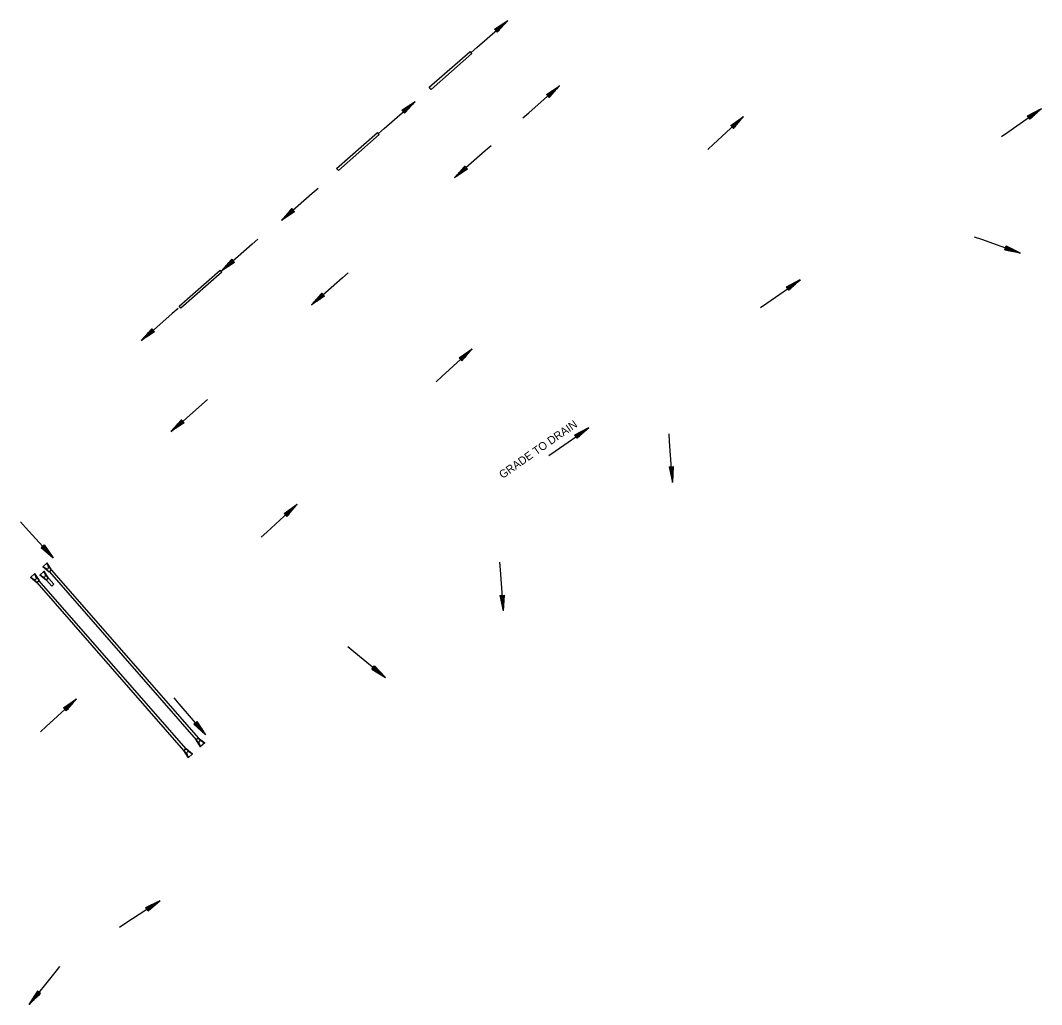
# Model space of a CAD drawing. Extents: x 1308292 to 1312792, y 238563 to 242743.
# Drawn here: x 1309034 to 1309800, y 239274 to 240011 of the extents above; entities that cross this region are included whole.
import ezdxf

# ---------------------------------------------------------------- set-up
doc = ezdxf.new("R2010")
doc.units = 0
for name, color, linetype in [('R_FES', 7, 'Continuous'), ('R_Flow Arrows', 7, 'Continuous'), ('R_Pipe Culvert', 7, 'Continuous')]:
    doc.layers.add(name, color=color, linetype=linetype)

msp = doc.modelspace()

# ---------------------------------------------------------------- linework, layer by layer
at = {"layer": 'R_FES'}
for p, q in [((1309051.19, 239601.87), (1309054.59, 239604.82)), ((1309055.54, 239601.86), (1309054.4, 239604.65)), ((1309057.54, 239599.55), (1309054.4, 239604.65)), ((1309057.85, 239599.54), (1309054.59, 239604.82)), ((1309054.59, 239604.82), (1309055.54, 239601.86)), ((1309042.01, 239593.8), (1309045.36, 239596.81)), ((1309046.36, 239593.87), (1309045.17, 239596.64)), ((1309048.41, 239591.6), (1309045.17, 239596.64)), ((1309048.71, 239591.59), (1309045.36, 239596.81)), ((1309045.36, 239596.81), (1309046.36, 239593.87)), ((1309048.89, 239595.75), (1309052.27, 239598.72)), ((1309049.08, 239595.91), (1309051.72, 239594.25)), ((1309053.71, 239592.11), (1309049.08, 239595.91)), ((1309055.96, 239597.9), (1309051.19, 239601.87)), ((1309054, 239600.36), (1309051.19, 239601.87)), ((1309051.38, 239602.04), (1309054, 239600.36)), ((1309055.98, 239598.2), (1309051.38, 239602.04)), ((1309053.24, 239595.76), (1309052.08, 239598.55)), ((1309055.26, 239593.47), (1309052.08, 239598.55)), ((1309055.56, 239593.46), (1309052.27, 239598.72)), ((1309052.27, 239598.72), (1309053.24, 239595.76)), ((1309057.85, 239599.54), (1309055.96, 239597.9)), ((1309055.98, 239598.2), (1309055.96, 239597.9)), ((1309055.98, 239598.2), (1309057.54, 239599.55)), ((1309057.54, 239599.55), (1309057.85, 239599.54)), ((1309046.85, 239589.92), (1309042.01, 239593.8)), ((1309044.85, 239592.34), (1309042.01, 239593.8)), ((1309042.2, 239593.97), (1309044.85, 239592.34)), ((1309046.87, 239590.22), (1309042.2, 239593.97)), ((1309048.71, 239591.59), (1309046.85, 239589.92)), ((1309046.87, 239590.22), (1309046.85, 239589.92)), ((1309046.87, 239590.22), (1309048.41, 239591.6)), ((1309048.41, 239591.6), (1309048.71, 239591.59)), ((1309053.69, 239591.81), (1309048.89, 239595.75)), ((1309051.72, 239594.25), (1309048.89, 239595.75)), ((1309055.56, 239593.46), (1309053.69, 239591.81)), ((1309053.71, 239592.11), (1309053.69, 239591.81)), ((1309053.71, 239592.11), (1309055.26, 239593.47)), ((1309055.26, 239593.47), (1309055.56, 239593.46)), ((1309165.89, 239472.22), (1309167.76, 239473.88)), ((1309167.74, 239473.57), (1309166.19, 239472.21)), ((1309167.74, 239473.57), (1309167.76, 239473.88)), ((1309167.74, 239473.57), (1309172.37, 239469.77)), ((1309167.76, 239473.88), (1309172.56, 239469.94)), ((1309156.74, 239464.17), (1309158.62, 239465.82)), ((1309158.59, 239465.52), (1309158.62, 239465.82)), ((1309158.62, 239465.82), (1309163.41, 239461.88)), ((1309165.89, 239472.22), (1309169.18, 239466.96)), ((1309166.19, 239472.21), (1309165.89, 239472.22)), ((1309166.19, 239472.21), (1309169.37, 239467.13)), ((1309168.21, 239469.92), (1309169.37, 239467.13)), ((1309169.18, 239466.96), (1309168.21, 239469.92)), ((1309172.56, 239469.94), (1309169.18, 239466.96)), ((1309169.73, 239471.43), (1309172.56, 239469.94)), ((1309172.37, 239469.77), (1309169.73, 239471.43)), ((1309156.74, 239464.17), (1309160.03, 239458.91)), ((1309157.04, 239464.16), (1309156.74, 239464.17)), ((1309158.59, 239465.52), (1309157.04, 239464.16)), ((1309157.04, 239464.16), (1309160.22, 239459.08)), ((1309158.59, 239465.52), (1309163.22, 239461.71)), ((1309159.07, 239461.86), (1309160.22, 239459.08)), ((1309160.03, 239458.91), (1309159.07, 239461.86)), ((1309163.41, 239461.88), (1309160.03, 239458.91)), ((1309160.59, 239463.37), (1309163.41, 239461.88)), ((1309163.22, 239461.71), (1309160.59, 239463.37))]:
    msp.add_line(p, q, dxfattribs=at)
for centre, major_axis in [((1309054.45, 239601.44), (-0.787, 0.862)), ((1309045.28, 239593.43), (-0.803, 0.846)), ((1309052.15, 239595.34), (-0.793, 0.856)), ((1309169.3, 239470.34), (0.793, -0.856)), ((1309160.15, 239462.29), (0.793, -0.856))]:
    msp.add_ellipse(centre, major_axis=major_axis, ratio=0.999949, start_param=2.010439, end_param=4.34099, dxfattribs=at)
at = {"layer": 'R_Flow Arrows'}
for p, q in [((1309389.78, 240004.61), (1309399.62, 240011.2)), ((1309391.78, 240002.32), (1309399.62, 240011.2)), ((1309389.78, 240004.61), (1309391.78, 240002.32)), ((1309428.61, 239955.75), (1309438.51, 239962.26)), ((1309428.61, 239955.75), (1309430.59, 239953.45)), ((1309430.59, 239953.45), (1309438.51, 239962.26)), ((1309320.34, 239943.9), (1309330.18, 239950.49)), ((1309322.34, 239941.61), (1309330.18, 239950.49)), ((1309320.34, 239943.9), (1309322.34, 239941.61)), ((1309789.1, 239939.65), (1309799.55, 239945.23)), ((1309790.86, 239937.17), (1309799.55, 239945.23)), ((1309566.69, 239932.4), (1309576.37, 239939.23)), ((1309568.74, 239930.16), (1309576.37, 239939.23)), ((1309790.86, 239937.17), (1309789.1, 239939.65)), ((1309566.69, 239932.4), (1309568.74, 239930.16)), ((1309367.56, 239902.12), (1309359.64, 239893.31)), ((1309369.54, 239899.82), (1309367.56, 239902.12)), ((1309369.54, 239899.82), (1309359.64, 239893.31)), ((1309237.92, 239870.22), (1309230, 239861.4)), ((1309239.9, 239867.91), (1309230, 239861.4)), ((1309239.9, 239867.91), (1309237.92, 239870.22)), ((1309772.02, 239839.47), (1309773.01, 239842.35)), ((1309773.01, 239842.35), (1309783.63, 239837.09)), ((1309772.02, 239839.47), (1309783.63, 239837.09)), ((1309192.87, 239832.29), (1309184.95, 239823.47)), ((1309194.85, 239829.98), (1309184.95, 239823.47)), ((1309194.85, 239829.98), (1309192.87, 239832.29)), ((1309608.4, 239811.51), (1309618.85, 239817.09)), ((1309610.16, 239809.04), (1309608.4, 239811.51)), ((1309610.16, 239809.04), (1309618.85, 239817.09)), ((1309260.41, 239806.9), (1309252.5, 239798.08)), ((1309262.39, 239804.59), (1309252.5, 239798.08)), ((1309262.39, 239804.59), (1309260.41, 239806.9)), ((1309132.96, 239780.2), (1309125.04, 239771.38)), ((1309134.94, 239777.89), (1309132.96, 239780.2)), ((1309134.94, 239777.89), (1309125.04, 239771.38)), ((1309363.25, 239758.42), (1309372.93, 239765.24)), ((1309365.3, 239756.18), (1309372.93, 239765.24)), ((1309363.25, 239758.42), (1309365.3, 239756.18)), ((1309155.14, 239712.05), (1309147.22, 239703.23)), ((1309157.12, 239709.74), (1309155.14, 239712.05)), ((1309157.12, 239709.74), (1309147.22, 239703.23)), ((1309449.89, 239700.65), (1309460.34, 239706.23)), ((1309451.66, 239698.17), (1309460.34, 239706.23)), ((1309451.66, 239698.17), (1309449.89, 239700.65)), ((1309520.58, 239676.66), (1309523.61, 239676.92)), ((1309520.58, 239676.66), (1309523.07, 239665.08)), ((1309523.61, 239676.92), (1309523.07, 239665.08)), ((1309232.14, 239641.88), (1309241.83, 239648.7)), ((1309232.14, 239641.88), (1309234.2, 239639.64)), ((1309234.2, 239639.64), (1309241.83, 239648.7)), ((1309052.23, 239618.35), (1309049.98, 239616.3)), ((1309049.98, 239616.3), (1309059.01, 239608.63)), ((1309052.23, 239618.35), (1309059.01, 239608.63)), ((1309393.79, 239580.47), (1309396.82, 239580.72)), ((1309396.82, 239580.72), (1309396.29, 239568.89)), ((1309393.79, 239580.47), (1309396.29, 239568.89)), ((1309297.89, 239525.23), (1309299.8, 239527.59)), ((1309299.8, 239527.59), (1309307.99, 239519.04)), ((1309297.89, 239525.23), (1309307.99, 239519.04)), ((1309066.77, 239496.16), (1309076.45, 239502.99)), ((1309068.82, 239493.92), (1309076.45, 239502.99)), ((1309066.77, 239496.16), (1309068.82, 239493.92)), ((1309166.69, 239485.99), (1309164.39, 239484.01)), ((1309164.39, 239484.01), (1309173.22, 239476.11)), ((1309166.69, 239485.99), (1309173.22, 239476.11)), ((1309128.53, 239346.79), (1309139.16, 239352.02)), ((1309130.21, 239344.26), (1309139.16, 239352.02)), ((1309130.21, 239344.26), (1309128.53, 239346.79)), ((1309047.12, 239284.1), (1309040.86, 239274.04)), ((1309049.48, 239282.17), (1309040.86, 239274.04)), ((1309049.48, 239282.17), (1309047.12, 239284.1))]:
    msp.add_line(p, q, dxfattribs=at)
for points in [[(1309372.16, 239987.17), (1309376.49, 239990.98), (1309399.62, 240011.2)], [(1309390.58, 240003.7), (1309395.26, 240007.79), (1309397.66, 240009.88)], [(1309390.98, 240003.24), (1309395.66, 240007.33), (1309398.06, 240009.42)], [(1309389.98, 240004.38), (1309391.75, 240005.93)], [(1309390.18, 240004.15), (1309393.71, 240007.25)], [(1309390.38, 240003.93), (1309395.06, 240008.02), (1309395.69, 240008.57)], [(1309391.18, 240003.01), (1309395.86, 240007.1), (1309396.48, 240007.65)], [(1309391.38, 240002.78), (1309394.92, 240005.88)], [(1309391.58, 240002.55), (1309393.35, 240004.1)], [(1309411.01, 239938.28), (1309415.32, 239942.1), (1309438.41, 239962.38)], [(1309428.81, 239955.52), (1309430.59, 239957.06)], [(1309429.01, 239955.29), (1309432.57, 239958.36)], [(1309429.2, 239955.06), (1309433.92, 239959.12), (1309434.55, 239959.66)], [(1309429.4, 239954.83), (1309434.12, 239958.89), (1309436.53, 239960.96)], [(1309429.8, 239954.37), (1309434.51, 239958.43), (1309436.93, 239960.49)], [(1309430, 239954.14), (1309434.71, 239958.2), (1309435.34, 239958.74)], [(1309430.2, 239953.91), (1309433.76, 239956.98)], [(1309302.73, 239926.46), (1309307.05, 239930.27), (1309330.18, 239950.49)], [(1309320.94, 239943.21), (1309325.62, 239947.31), (1309326.25, 239947.85)], [(1309321.14, 239942.99), (1309325.82, 239947.08), (1309328.22, 239949.17)], [(1309321.54, 239942.53), (1309326.22, 239946.62), (1309328.62, 239948.71)], [(1309430.39, 239953.68), (1309432.18, 239955.21)], [(1309320.54, 239943.67), (1309322.31, 239945.22)], [(1309320.74, 239943.44), (1309324.28, 239946.54)], [(1309321.74, 239942.3), (1309326.42, 239946.39), (1309327.05, 239946.94)], [(1309321.94, 239942.07), (1309325.48, 239945.16)], [(1309322.14, 239941.84), (1309323.91, 239943.39)], [(1309769.69, 239924.25), (1309774.43, 239927.54), (1309799.63, 239945.1)], [(1309789.27, 239939.4), (1309791.19, 239940.77)], [(1309789.45, 239939.15), (1309793.28, 239941.88)], [(1309789.63, 239938.91), (1309794.69, 239942.51), (1309795.36, 239943)], [(1309789.8, 239938.66), (1309794.87, 239942.27), (1309797.45, 239944.12)], [(1309790.16, 239938.16), (1309795.22, 239941.77), (1309797.8, 239943.63)], [(1309790.33, 239937.92), (1309795.4, 239941.52), (1309796.07, 239942.01)], [(1309790.51, 239937.67), (1309794.34, 239940.4)], [(1309549.5, 239914.54), (1309553.73, 239918.45), (1309576.37, 239939.23)], [(1309566.89, 239932.18), (1309568.62, 239933.77)], [(1309567.1, 239931.96), (1309570.56, 239935.13)], [(1309567.3, 239931.73), (1309571.88, 239935.94), (1309572.5, 239936.5)], [(1309567.51, 239931.51), (1309572.09, 239935.71), (1309574.44, 239937.86)], [(1309567.92, 239931.06), (1309572.5, 239935.26), (1309574.85, 239937.41)], [(1309568.12, 239930.84), (1309572.71, 239935.04), (1309573.32, 239935.6)], [(1309568.33, 239930.61), (1309571.79, 239933.79)], [(1309790.68, 239937.42), (1309792.6, 239938.78)], [(1309568.54, 239930.39), (1309570.27, 239931.98)], [(1309387.14, 239917.29), (1309382.82, 239913.47), (1309359.74, 239893.19)], [(1309368.35, 239901.2), (1309363.64, 239897.15), (1309361.22, 239895.08)], [(1309368.75, 239900.74), (1309364.03, 239896.68), (1309361.62, 239894.62)], [(1309368.15, 239901.43), (1309363.44, 239897.38), (1309362.81, 239896.84)], [(1309368.95, 239900.51), (1309364.23, 239896.45), (1309363.6, 239895.91)], [(1309367.95, 239901.66), (1309364.39, 239898.6)], [(1309369.14, 239900.28), (1309365.58, 239897.21)], [(1309367.76, 239901.89), (1309365.97, 239900.36)], [(1309369.34, 239900.05), (1309367.56, 239898.52)], [(1309257.5, 239885.39), (1309253.18, 239881.57), (1309230.1, 239861.29)], [(1309238.71, 239869.3), (1309234, 239865.24), (1309231.58, 239863.17)], [(1309239.11, 239868.83), (1309234.39, 239864.78), (1309231.98, 239862.71)], [(1309238.51, 239869.53), (1309233.8, 239865.47), (1309233.17, 239864.93)], [(1309239.31, 239868.6), (1309234.59, 239864.55), (1309233.96, 239864.01)], [(1309238.31, 239869.76), (1309234.75, 239866.69)], [(1309239.5, 239868.37), (1309235.94, 239865.31)], [(1309238.12, 239869.99), (1309236.33, 239868.45)], [(1309239.7, 239868.14), (1309237.92, 239866.61)], [(1309749.2, 239849.19), (1309754.63, 239847.24), (1309783.58, 239836.95)], [(1309212.45, 239847.46), (1309208.13, 239843.64), (1309185.05, 239823.36)], [(1309772.62, 239841.2), (1309778.49, 239839.18), (1309781.51, 239838.15)], [(1309772.71, 239841.49), (1309778.59, 239839.47), (1309779.38, 239839.2)], [(1309772.81, 239841.78), (1309777.26, 239840.25)], [(1309772.91, 239842.06), (1309775.13, 239841.3)], [(1309772.12, 239839.76), (1309774.34, 239839)], [(1309772.22, 239840.05), (1309776.66, 239838.52)], [(1309772.32, 239840.34), (1309778.2, 239838.31), (1309778.99, 239838.05)], [(1309772.42, 239840.63), (1309778.3, 239838.6), (1309781.31, 239837.58)], [(1309193.66, 239831.36), (1309188.95, 239827.31), (1309186.53, 239825.24)], [(1309194.06, 239830.9), (1309189.34, 239826.85), (1309186.93, 239824.78)], [(1309193.46, 239831.6), (1309188.75, 239827.54), (1309188.12, 239827)], [(1309194.26, 239830.67), (1309189.54, 239826.62), (1309188.91, 239826.08)], [(1309193.26, 239831.83), (1309189.7, 239828.76)], [(1309194.45, 239830.44), (1309190.89, 239827.38)], [(1309193.07, 239832.06), (1309191.28, 239830.52)], [(1309194.65, 239830.21), (1309192.87, 239828.68)], [(1309280, 239822.07), (1309275.68, 239818.25), (1309252.6, 239797.97)], [(1309588.99, 239796.12), (1309593.73, 239799.4), (1309618.94, 239816.97)], [(1309608.57, 239811.26), (1309610.49, 239812.63)], [(1309608.75, 239811.02), (1309612.58, 239813.74)], [(1309608.93, 239810.77), (1309613.99, 239814.38), (1309614.67, 239814.86)], [(1309609.1, 239810.52), (1309614.17, 239814.13), (1309616.75, 239815.98)], [(1309609.46, 239810.03), (1309614.52, 239813.63), (1309617.11, 239815.49)], [(1309609.63, 239809.78), (1309614.7, 239813.39), (1309615.37, 239813.87)], [(1309609.81, 239809.53), (1309613.64, 239812.26)], [(1309609.99, 239809.28), (1309611.9, 239810.65)], [(1309261.21, 239805.98), (1309256.49, 239801.92), (1309254.07, 239799.85)], [(1309261.6, 239805.52), (1309256.89, 239801.46), (1309254.47, 239799.39)], [(1309261.01, 239806.21), (1309256.29, 239802.15), (1309255.66, 239801.61)], [(1309261.8, 239805.28), (1309257.09, 239801.23), (1309256.45, 239800.69)], [(1309260.81, 239806.44), (1309257.25, 239803.37)], [(1309262, 239805.05), (1309258.44, 239801.99)], [(1309260.61, 239806.67), (1309258.83, 239805.14)], [(1309262.2, 239804.82), (1309260.41, 239803.29)], [(1309152.54, 239795.37), (1309148.23, 239791.55), (1309125.15, 239771.27)], [(1309133.36, 239779.74), (1309129.79, 239776.67)], [(1309133.16, 239779.97), (1309131.38, 239778.44)], [(1309133.75, 239779.28), (1309129.04, 239775.22), (1309126.62, 239773.15)], [(1309134.15, 239778.82), (1309129.44, 239774.76), (1309127.02, 239772.69)], [(1309133.55, 239779.51), (1309128.84, 239775.45), (1309128.21, 239774.91)], [(1309134.35, 239778.58), (1309129.63, 239774.53), (1309129, 239773.99)], [(1309134.55, 239778.35), (1309130.98, 239775.29)], [(1309134.74, 239778.12), (1309132.96, 239776.59)], [(1309346.06, 239740.56), (1309350.29, 239744.47), (1309372.93, 239765.24)], [(1309363.45, 239758.19), (1309365.18, 239759.78)], [(1309363.66, 239757.97), (1309367.12, 239761.15)], [(1309363.86, 239757.75), (1309368.44, 239761.95), (1309369.06, 239762.51)], [(1309364.07, 239757.52), (1309368.65, 239761.73), (1309371, 239763.87)], [(1309364.48, 239757.07), (1309369.06, 239761.28), (1309371.41, 239763.42)], [(1309364.68, 239756.85), (1309369.26, 239761.05), (1309369.88, 239761.61)], [(1309364.89, 239756.63), (1309368.35, 239759.8)], [(1309365.1, 239756.4), (1309366.83, 239757.99)], [(1309174.72, 239727.22), (1309170.4, 239723.4), (1309147.32, 239703.12)], [(1309155.93, 239711.12), (1309151.22, 239707.07), (1309148.8, 239705)], [(1309156.33, 239710.66), (1309151.61, 239706.61), (1309149.2, 239704.54)], [(1309155.73, 239711.35), (1309151.02, 239707.3), (1309150.39, 239706.76)], [(1309155.53, 239711.58), (1309151.97, 239708.52)], [(1309155.34, 239711.82), (1309153.55, 239710.28)], [(1309156.53, 239710.43), (1309151.81, 239706.38), (1309151.18, 239705.83)], [(1309156.72, 239710.2), (1309153.16, 239707.14)], [(1309156.92, 239709.97), (1309155.14, 239708.44)], [(1309430.48, 239685.25), (1309435.22, 239688.53), (1309460.43, 239706.1)], [(1309450.42, 239699.9), (1309455.49, 239703.51), (1309456.16, 239703.99)], [(1309450.6, 239699.65), (1309455.66, 239703.26), (1309458.25, 239705.12)], [(1309450.95, 239699.16), (1309456.02, 239702.77), (1309458.6, 239704.62)], [(1309451.13, 239698.91), (1309456.19, 239702.52), (1309456.87, 239703.01)], [(1309450.07, 239700.4), (1309451.98, 239701.76)], [(1309450.25, 239700.15), (1309454.07, 239702.88)], [(1309451.31, 239698.66), (1309455.13, 239701.39)], [(1309451.48, 239698.42), (1309453.4, 239699.78)], [(1309520.27, 239701.46), (1309520.67, 239695.71), (1309522.92, 239665.07)], [(1309520.88, 239676.69), (1309521.08, 239674.34)], [(1309521.18, 239676.71), (1309521.58, 239672.03)], [(1309521.49, 239676.74), (1309522.01, 239670.54), (1309522.08, 239669.71)], [(1309521.79, 239676.76), (1309522.31, 239670.57), (1309522.58, 239667.4)], [(1309522.39, 239676.81), (1309522.92, 239670.62), (1309523.19, 239667.45)], [(1309522.7, 239676.84), (1309523.22, 239670.64), (1309523.29, 239669.82)], [(1309523, 239676.87), (1309523.39, 239672.18)], [(1309523.3, 239676.89), (1309523.5, 239674.55)], [(1309214.95, 239624.02), (1309219.19, 239627.93), (1309241.83, 239648.7)], [(1309232.35, 239641.66), (1309234.08, 239643.25)], [(1309232.55, 239641.43), (1309236.02, 239644.61)], [(1309232.76, 239641.21), (1309237.34, 239645.41), (1309237.96, 239645.97)], [(1309232.97, 239640.98), (1309237.55, 239645.19), (1309239.9, 239647.33)], [(1309233.38, 239640.54), (1309237.96, 239644.74), (1309240.31, 239646.88)], [(1309233.58, 239640.31), (1309238.16, 239644.52), (1309238.78, 239645.08)], [(1309233.79, 239640.09), (1309237.25, 239643.27)], [(1309034.45, 239635.62), (1309038.34, 239631.37), (1309059.01, 239608.63)], [(1309233.99, 239639.86), (1309235.73, 239641.45)], [(1309050.21, 239616.51), (1309051.79, 239614.77)], [(1309050.43, 239616.71), (1309053.59, 239613.23)], [(1309050.66, 239616.92), (1309054.84, 239612.32), (1309055.4, 239611.7)], [(1309050.88, 239617.12), (1309055.06, 239612.52), (1309057.2, 239610.16)], [(1309051.33, 239617.53), (1309055.51, 239612.93), (1309057.65, 239610.57)], [(1309051.56, 239617.73), (1309055.74, 239613.13), (1309056.3, 239612.52)], [(1309051.78, 239617.94), (1309054.94, 239614.46)], [(1309052.01, 239618.14), (1309053.59, 239616.4)], [(1309393.48, 239605.27), (1309393.89, 239599.52), (1309396.14, 239568.88)], [(1309395, 239580.57), (1309395.52, 239574.38), (1309395.8, 239571.21)], [(1309395.61, 239580.62), (1309396.13, 239574.43), (1309396.4, 239571.26)], [(1309395.91, 239580.65), (1309396.43, 239574.45), (1309396.5, 239573.62)], [(1309396.22, 239580.67), (1309396.61, 239575.99)], [(1309396.52, 239580.7), (1309396.72, 239578.36)], [(1309394.09, 239580.5), (1309394.29, 239578.15)], [(1309394.4, 239580.52), (1309394.79, 239575.84)], [(1309394.7, 239580.55), (1309395.22, 239574.35), (1309395.29, 239573.52)], [(1309279.74, 239542.13), (1309284.17, 239538.45), (1309307.89, 239518.92)], [(1309299.42, 239527.12), (1309303.07, 239524.17)], [(1309299.61, 239527.36), (1309301.44, 239525.88)], [(1309298.08, 239525.46), (1309299.91, 239523.99)], [(1309298.27, 239525.7), (1309301.93, 239522.75)], [(1309298.46, 239525.94), (1309303.3, 239522.03), (1309303.95, 239521.51)], [(1309298.65, 239526.17), (1309303.49, 239522.27), (1309305.98, 239520.28)], [(1309299.03, 239526.65), (1309303.87, 239522.75), (1309306.36, 239520.76)], [(1309299.22, 239526.88), (1309304.06, 239522.98), (1309304.71, 239522.46)], [(1309049.58, 239478.3), (1309053.81, 239482.21), (1309076.45, 239502.99)], [(1309066.97, 239495.94), (1309068.7, 239497.53)], [(1309067.18, 239495.71), (1309070.64, 239498.89)], [(1309067.38, 239495.49), (1309071.96, 239499.69), (1309072.58, 239500.26)], [(1309067.59, 239495.27), (1309072.17, 239499.47), (1309074.52, 239501.62)], [(1309068, 239494.82), (1309072.58, 239499.02), (1309074.93, 239501.17)], [(1309068.21, 239494.59), (1309072.79, 239498.8), (1309073.4, 239499.36)], [(1309068.41, 239494.37), (1309071.87, 239497.55)], [(1309149.35, 239503.71), (1309153.13, 239499.36), (1309173.22, 239476.11)], [(1309068.62, 239494.15), (1309070.35, 239495.74)], [(1309164.62, 239484.2), (1309166.16, 239482.43)], [(1309164.85, 239484.4), (1309167.92, 239480.85)], [(1309165.08, 239484.6), (1309169.14, 239479.9), (1309169.69, 239479.27)], [(1309165.31, 239484.8), (1309169.37, 239480.1), (1309171.45, 239477.69)], [(1309165.77, 239485.2), (1309169.84, 239480.49), (1309171.91, 239478.08)], [(1309166, 239485.4), (1309170.07, 239480.69), (1309170.61, 239480.06)], [(1309166.23, 239485.6), (1309169.3, 239482.04)], [(1309166.46, 239485.8), (1309168, 239484.02)], [(1309108.62, 239332.05), (1309113.47, 239335.17), (1309139.24, 239351.89)], [(1309128.7, 239346.54), (1309130.65, 239347.84)], [(1309128.86, 239346.29), (1309132.78, 239348.89)], [(1309129.03, 239346.03), (1309134.21, 239349.47), (1309134.9, 239349.93)], [(1309129.2, 239345.78), (1309134.38, 239349.22), (1309137.03, 239350.98)], [(1309129.54, 239345.27), (1309134.72, 239348.71), (1309137.36, 239350.48)], [(1309129.71, 239345.02), (1309134.89, 239348.46), (1309135.58, 239348.92)], [(1309129.87, 239344.77), (1309133.79, 239347.36)], [(1309130.04, 239344.51), (1309132, 239345.81)], [(1309063.78, 239302.43), (1309060.19, 239297.92), (1309040.98, 239273.95)], [(1309048.07, 239283.33), (1309044.13, 239278.52), (1309042.1, 239276.06)], [(1309048.54, 239282.94), (1309044.6, 239278.13), (1309042.57, 239275.67)], [(1309047.83, 239283.52), (1309043.89, 239278.71), (1309043.36, 239278.07)], [(1309048.77, 239282.75), (1309044.83, 239277.94), (1309044.3, 239277.29)], [(1309047.59, 239283.71), (1309044.62, 239280.07)], [(1309047.36, 239283.9), (1309045.87, 239282.09)], [(1309049.01, 239282.56), (1309046.03, 239278.92)], [(1309049.24, 239282.36), (1309047.75, 239280.54)]]:
    msp.add_lwpolyline(points, dxfattribs=at)
at = {"layer": 'R_Pipe Culvert'}
for p, q in [((1309340.82, 239961.09), (1309371.5, 239987.92)), ((1309342.13, 239959.58), (1309372.82, 239986.42)), ((1309372.82, 239986.42), (1309371.5, 239987.92)), ((1309342.13, 239959.58), (1309340.82, 239961.09)), ((1309271.38, 239900.38), (1309302.07, 239927.21)), ((1309303.38, 239925.71), (1309272.69, 239898.87)), ((1309303.38, 239925.71), (1309302.07, 239927.21)), ((1309272.69, 239898.87), (1309271.38, 239900.38)), ((1309153.41, 239797.24), (1309184.1, 239824.07)), ((1309185.42, 239822.56), (1309154.73, 239795.73)), ((1309185.42, 239822.56), (1309184.1, 239824.07)), ((1309154.73, 239795.73), (1309153.41, 239797.24)), ((1309056.14, 239598.06), (1309166.07, 239472.39)), ((1309057.66, 239599.37), (1309167.58, 239473.7)), ((1309156.94, 239464.33), (1309047.04, 239590.08)), ((1309158.42, 239465.66), (1309048.52, 239591.42)), ((1309057.86, 239587.46), (1309053.87, 239591.97)), ((1309059.36, 239588.79), (1309055.38, 239593.29)), ((1309057.86, 239587.46), (1309059.36, 239588.79))]:
    msp.add_line(p, q, dxfattribs=at)

# ---------------------------------------------------------------- texts
at = {"layer": 'R_Flow Arrows'}
msp.add_text('GRADE TO DRAIN', height=6, rotation=35.01893, dxfattribs=at).set_placement((1309395.78, 239667.64))

doc.saveas('drawing.dxf')
